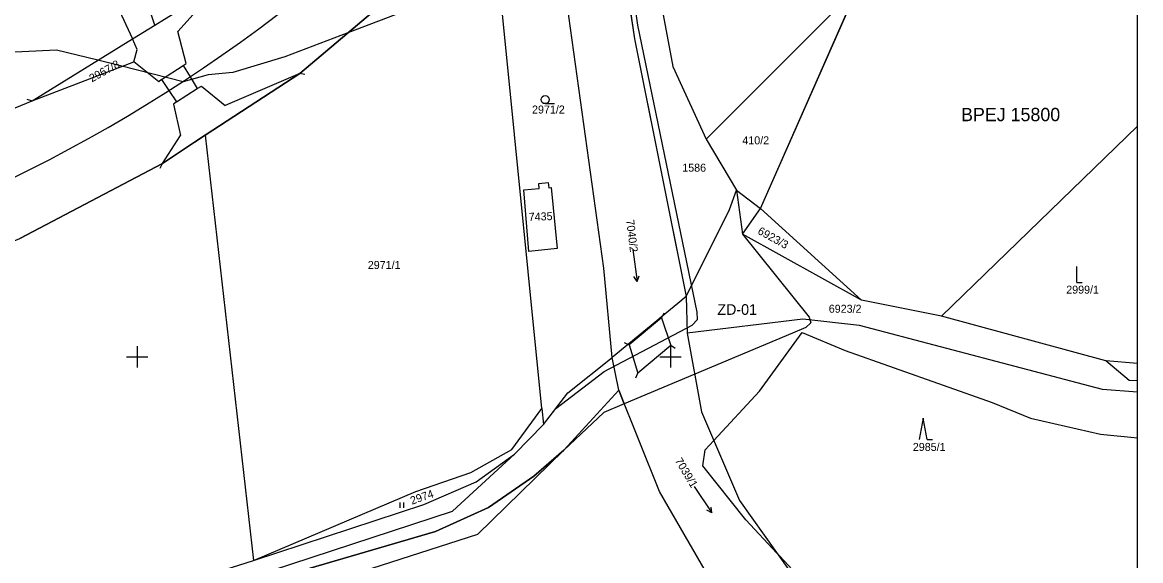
# Model space of a CAD drawing. Extents: x -800194 to -799297, y -1007177 to -1006761.
# Drawn here: x -799521.5 to -799311.8, y -1007038.2 to -1006937.3 of the extents above; entities that cross this region are included whole.
import ezdxf

# ---------------------------------------------------------------- set-up
doc = ezdxf.new("R2010")
doc.units = 0
for name, color, linetype in [('02_Osa_koleje', 7, 'Continuous'), ('BPEJ', 7, 'Continuous'), ('Dočasné zábory', 7, 'Continuous'), ('Dočasné zábory - čísla', 7, 'Continuous'), ('Legenda 1', 7, 'Continuous'), ('Pozemky SŽDC', 7, 'Continuous'), ('Ramove udaje', 7, 'Continuous'), ('Vrstva 53', 7, 'Continuous'), ('Vrstva 55', 7, 'Continuous'), ('Vrstva 56', 7, 'Continuous'), ('Vrstva 57', 7, 'Continuous'), ('Vrstva 58', 7, 'Continuous')]:
    doc.layers.add(name, color=color, linetype=linetype)

msp = doc.modelspace()

# ---------------------------------------------------------------- linework, layer by layer
at = {"layer": '02_Osa_koleje'}
msp.add_arc((-799651.02, -1006703.89), 292, 255.6249, 308.2052, dxfattribs=at)
at = {"layer": 'BPEJ'}
for points in [[(-799407.82, -1006932.95), (-799406.72, -1006940.36), (-799400.51, -1006971.29), (-799397.01, -1006988.73), (-799388.9, -1006972.36), (-799387.62, -1006968.78), (-799383.1, -1006972.22), (-799364.81, -1006930.69), (-799352.19, -1006902.04), (-799328.67, -1006848.61), (-799327.63, -1006846.25), (-799317.77, -1006827.17), (-799311.83, -1006815.65), (-799311.92, -1006815.63), (-799329.14, -1006812.3)], [(-799433.31, -1006923), (-799445.59, -1006934.44), (-799448.98, -1006934.86), (-799460.49, -1006939.26), (-799472.28, -1006943.76), (-799482.03, -1006946.72), (-799486.69, -1006947.15), (-799491.35, -1006948.42), (-799502.85, -1006945.54), (-799507.36, -1006944.41), (-799515.07, -1006942.49), (-799532.02, -1006943.33), (-799567.6, -1006955.2), (-799570.57, -1006956.47), (-799576.08, -1006956.47), (-799584.12, -1006958.16), (-799598.95, -1006964.52), (-799621.99, -1006980.43), (-799662.84, -1007008.64), (-799667.29, -1007011.71), (-799675.63, -1007017.47), (-799679.12, -1007020.67)], [(-799369.92, -1007046.57), (-799374, -1007043.32), (-799379.5, -1007037.38), (-799380.03, -1007036.82), (-799385.86, -1007030.61), (-799393.91, -1007020.44), (-799393.48, -1007017.47), (-799391.85, -1007015.71), (-799383.32, -1007006.46), (-799375.27, -1006995.44), (-799367.22, -1006998.83), (-799339.68, -1007008.58), (-799332.48, -1007011.54), (-799319.35, -1007014.51), (-799312.4, -1007015.23)]]:
    msp.add_lwpolyline(points, dxfattribs=at)
at = {"layer": 'Dočasné zábory'}
for points in [[(-799407.32, -1006903.81), (-799399.52, -1006945.6), (-799393.3, -1006959.22), (-799387.62, -1006968.78), (-799386.5, -1006977.04), (-799373.97, -1006992.55), (-799373.66, -1006993.66), (-799374.58, -1006994.49), (-799377.09, -1006995.58), (-799408.65, -1007008.83), (-799409.68, -1007006.29), (-799420, -1007017.54), (-799425.58, -1007022.42), (-799434.1, -1007028.26), (-799444.02, -1007032.78), (-799478.24, -1007042.75)], [(-799550.16, -1007064.74), (-799440.86, -1007028.93), (-799429.23, -1007018.29), (-799423.8, -1007012.71), (-799421.5, -1007009.7), (-799412.39, -1007002.78), (-799395.92, -1006994.07), (-799394.94, -1006993.03), (-799394.95, -1006991.66), (-799406.07, -1006937.82), (-799408.05, -1006924.38)]]:
    msp.add_lwpolyline(points, dxfattribs=at)
msp.add_lwpolyline([(-799605.71, -1007090.19), (-799595.06, -1007084.22), (-799551.8, -1007065.45), (-799478.24, -1007042.75), (-799444.02, -1007032.78), (-799434.1, -1007028.26), (-799425.58, -1007022.42), (-799420, -1007017.54), (-799409.68, -1007006.29), (-799408.65, -1007008.83), (-799412.5, -1007010.44), (-799420, -1007017.54), (-799436.16, -1007033.34), (-799548.49, -1007069.46), (-799592.16, -1007088.85), (-799605.02, -1007095.33)], close=True, dxfattribs=at)
at = {"layer": 'Legenda 1'}
msp.add_lwpolyline([(-800193.4, -1007176.65), (-799312.4, -1007176.65), (-799312.4, -1006766.65), (-800193.4, -1006766.65)], close=True, dxfattribs=at)
at = {"layer": 'Pozemky SŽDC'}
msp.add_lwpolyline([(-799559.64, -1006968.48), (-799519.68, -1006952.01), (-799500.87, -1006940.41), (-799496.64, -1006937.8), (-799494.85, -1006936.7), (-799484.52, -1006930.32), (-799457.99, -1006908.8), (-799435, -1006885.17), (-799430.26, -1006880.27), (-799425.53, -1006875.38), (-799422.55, -1006864.36), (-799416.75, -1006858.8), (-799395.76, -1006879.37), (-799413.75, -1006898.23), (-799418.41, -1006902.53), (-799423.07, -1006906.83), (-799433.4, -1006916.39), (-799469.5, -1006946.86), (-799487.22, -1006958.47), (-799495.25, -1006963.74), (-799521.98, -1006977.8)], dxfattribs=at)
at = {"layer": 'Ramove udaje'}
for p, q in [((-799500, -1006998), (-799500, -1007002)), ((-799400, -1006998), (-799400, -1007002)), ((-799502, -1007000), (-799500, -1007000)), ((-799500, -1007000), (-799498, -1007000)), ((-799402, -1007000), (-799400, -1007000)), ((-799400, -1007000), (-799398, -1007000))]:
    msp.add_line(p, q, dxfattribs=at)
at = {"layer": 'Vrstva 53'}
for points in [[(-799559.64, -1006968.48), (-799519.68, -1006952.01), (-799500.87, -1006940.41), (-799496.64, -1006937.8), (-799494.85, -1006936.7), (-799484.52, -1006930.32), (-799457.99, -1006908.8), (-799435, -1006885.17), (-799430.26, -1006880.27), (-799425.53, -1006875.38), (-799422.55, -1006864.36), (-799390.88, -1006834), (-799358.35, -1006806.65), (-799352.29, -1006801.56), (-799330.91, -1006783.58), (-799314.24, -1006766.65)], [(-799312.4, -1006791.98), (-799331.37, -1006811.87), (-799413.75, -1006898.23), (-799418.41, -1006902.53), (-799423.07, -1006906.83), (-799433.4, -1006916.39), (-799469.5, -1006946.86), (-799487.22, -1006958.47), (-799495.25, -1006963.74), (-799521.98, -1006977.8)]]:
    msp.add_lwpolyline(points, dxfattribs=at)
at = {"layer": 'Vrstva 55'}
for p, q in [((-799424.1, -1007009.73), (-799433.4, -1006916.39)), ((-799393.3, -1006959.22), (-799364.81, -1006930.69)), ((-799383.1, -1006972.22), (-799364.81, -1006930.69)), ((-799496.64, -1006937.8), (-799494.85, -1006936.7)), ((-799500.87, -1006940.41), (-799496.64, -1006937.8)), ((-799519.68, -1006952.01), (-799500.87, -1006940.41)), ((-799312.4, -1006956.76), (-799349.19, -1006992.39)), ((-799487.22, -1006958.47), (-799478.14, -1007038.23)), ((-799393.3, -1006959.22), (-799387.62, -1006968.78)), ((-799387.62, -1006968.78), (-799383.1, -1006972.22)), ((-799364.19, -1006989.42), (-799383.1, -1006972.22)), ((-799397.01, -1006988.73), (-799398.6, -1006990.04)), ((-799397.01, -1006988.73), (-799396.86, -1006995.59)), ((-799349.19, -1006992.39), (-799364.19, -1006989.42)), ((-799318.36, -1007000.74), (-799349.19, -1006992.39)), ((-799409.68, -1007006.29), (-799410.89, -1007000.14)), ((-799312.4, -1007001.25), (-799318.36, -1007000.74)), ((-799424.1, -1007009.73), (-799423.8, -1007012.71))]:
    msp.add_line(p, q, dxfattribs=at)
for points in [[(-799413.75, -1006898.23), (-799411.99, -1006904.75), (-799406.72, -1006940.36), (-799397.01, -1006988.73)], [(-799496.64, -1006937.8), (-799507.65, -1006904.69), (-799515.98, -1006907.74), (-799500.87, -1006940.41)], [(-799407.32, -1006903.81), (-799399.52, -1006945.6), (-799393.3, -1006959.22)], [(-799410.89, -1007000.14), (-799412.5, -1006983.38), (-799423.07, -1006906.83)], [(-799487.22, -1006958.47), (-799469.5, -1006946.86), (-799433.4, -1006916.39)], [(-799519.68, -1006952.01), (-799500.6, -1006944.68), (-799499.96, -1006942.39), (-799500.87, -1006940.41)], [(-799667.43, -1006981.06), (-799637.16, -1006982.06), (-799603.07, -1006978.39), (-799559.64, -1006968.48), (-799519.68, -1006952.01)], [(-799599.63, -1007001.65), (-799583.97, -1006998.26), (-799572.22, -1006995.8), (-799546.71, -1006987.83), (-799521.98, -1006977.8), (-799495.25, -1006963.74), (-799489.22, -1006959.79), (-799487.22, -1006958.47)], [(-799422.35, -1006968.27), (-799421.24, -1006979.68), (-799426.55, -1006980.27), (-799427.48, -1006968.72), (-799424.58, -1006968.47), (-799424.66, -1006967.5), (-799422.89, -1006967.35), (-799422.79, -1006968.31), (-799422.35, -1006968.27)], [(-799397.01, -1006988.73), (-799388.9, -1006972.36), (-799387.62, -1006968.78)], [(-799364.19, -1006989.42), (-799386.5, -1006977.04), (-799383.1, -1006972.22)], [(-799398.6, -1006990.04), (-799401.7, -1006992.59), (-799402.52, -1006993.26), (-799407.79, -1006997.59), (-799410.89, -1007000.14)], [(-799312.4, -1007006.62), (-799318.99, -1007006.15), (-799364.52, -1006994.13), (-799375.17, -1006992.97), (-799396.86, -1006995.59)], [(-799396.86, -1006995.59), (-799394.17, -1007010.32), (-799387.01, -1007026.98), (-799377.82, -1007039.94), (-799372.89, -1007045.05)], [(-799423.8, -1007012.71), (-799419.24, -1007006.74), (-799410.89, -1007000.14)], [(-799312.4, -1007004.53), (-799313.97, -1007004.43), (-799318.36, -1007000.74)], [(-799409.68, -1007006.29), (-799420, -1007017.54), (-799425.58, -1007022.42), (-799434.1, -1007028.26), (-799444.02, -1007032.78), (-799478.24, -1007042.75), (-799552.64, -1007065.71), (-799567.11, -1007070.01), (-799588.9, -1007077.33), (-799598.09, -1007080.87), (-799606.31, -1007085.7)], [(-799387.89, -1007049.68), (-799402.01, -1007025.25), (-799409.68, -1007006.29)], [(-799478.14, -1007038.23), (-799447.72, -1007025.26), (-799437.44, -1007021.73), (-799429.75, -1007017.42), (-799424.1, -1007009.73)], [(-799478.14, -1007038.23), (-799446.24, -1007027.7), (-799436.41, -1007023.44), (-799429.23, -1007018.29), (-799423.8, -1007012.71)], [(-799584.37, -1007069.36), (-799568.78, -1007065.44), (-799553.44, -1007061.89), (-799480.9, -1007039.1), (-799478.14, -1007038.23)]]:
    msp.add_lwpolyline(points, dxfattribs=at)
at = {"layer": 'Vrstva 56'}
for p, q in [((-799484.52, -1006930.32), (-799492.32, -1006939.01)), ((-799490.79, -1006945.02), (-799492.32, -1006939.01)), ((-799495.94, -1006948.45), (-799500.6, -1006944.68)), ((-799491.36, -1006945.39), (-799490.79, -1006945.02)), ((-799495.39, -1006948.04), (-799491.36, -1006945.39)), ((-799491.36, -1006945.39), (-799490.06, -1006947.5)), ((-799469.5, -1006946.86), (-799483.5, -1006952.89)), ((-799468.52, -1006947.07), (-799469.5, -1006946.86)), ((-799495.39, -1006948.04), (-799495.94, -1006948.45)), ((-799495.39, -1006948.04), (-799494.03, -1006950.08)), ((-799490.06, -1006947.5), (-799488.7, -1006949.72)), ((-799488.7, -1006949.72), (-799487.92, -1006949.28)), ((-799487.92, -1006949.28), (-799483.5, -1006952.89)), ((-799494.03, -1006950.08), (-799492.59, -1006952.23)), ((-799492.59, -1006952.23), (-799488.7, -1006949.72)), ((-799520.63, -1006951.68), (-799519.68, -1006952.01)), ((-799492.59, -1006952.23), (-799493.13, -1006952.62)), ((-799493.13, -1006952.62), (-799491.86, -1006958.5)), ((-799495.25, -1006963.74), (-799491.86, -1006958.5)), ((-799495.67, -1006964.65), (-799495.25, -1006963.74)), ((-799401.66, -1006992.7), (-799407.73, -1006997.77)), ((-799401.22, -1006991.8), (-799401.66, -1006992.7)), ((-799401.66, -1006992.7), (-799399.93, -1006997.9)), ((-799408.64, -1006997.35), (-799407.73, -1006997.77)), ((-799407.73, -1006997.77), (-799406.07, -1007003.06)), ((-799399.93, -1006997.9), (-799406.07, -1007003.06)), ((-799399.1, -1006998.46), (-799399.93, -1006997.9)), ((-799406.49, -1007003.97), (-799406.07, -1007003.06))]:
    msp.add_line(p, q, dxfattribs=at)
at = {"layer": 'Vrstva 58'}
for p, q in [((-799423.48, -1006952.54), (-799421.73, -1006952.54)), ((-799407.01, -1006979.92), (-799406.22, -1006985.87)), ((-799406.22, -1006985.87), (-799406.85, -1006984.97)), ((-799406.22, -1006985.87), (-799405.86, -1006984.83)), ((-799323.8, -1006986.09), (-799323.8, -1006983.09)), ((-799323.8, -1006986.09), (-799322.8, -1006986.09)), ((-799352.59, -1007011.5), (-799353.34, -1007015.5)), ((-799351.84, -1007015.5), (-799352.59, -1007011.5)), ((-799351.84, -1007015.5), (-799350.84, -1007015.5)), ((-799395.57, -1007024.31), (-799392.21, -1007029.28)), ((-799450.66, -1007028.34), (-799450.66, -1007027.34)), ((-799449.99, -1007028.34), (-799449.99, -1007027.34)), ((-799392.21, -1007029.28), (-799393.18, -1007028.75)), ((-799392.21, -1007029.28), (-799392.35, -1007028.19))]:
    msp.add_line(p, q, dxfattribs=at)
msp.add_circle((-799423.48, -1006951.79), 0.75, dxfattribs=at)

# ---------------------------------------------------------------- texts
at = {"layer": 'BPEJ'}
msp.add_text('BPEJ 15800', height=2.5, dxfattribs=at).set_placement((-799345.5, -1006955.83))
at = {"layer": 'Dočasné zábory - čísla'}
msp.add_text('ZD-01', height=2, rotation=0, dxfattribs=at).set_placement((-799391.19, -1006992.14))
at = {"layer": 'Vrstva 57'}
for s, rotation, p in [('2967/8', 29, (-799508.45, -1006948.57)), ('7435', 2, (-799426.53, -1006974.53)), ('7040/2', 277, (-799408.3, -1006974.37)), ('6923/3', 331, (-799383.77, -1006976.86)), ('7039/1', 301, (-799399.22, -1007019.47)), ('2974', 19, (-799448.46, -1007027.75))]:
    msp.add_text(s, height=1.5, rotation=rotation, dxfattribs=at).set_placement(p)
for s, p in [('2971/2', (-799425.94, -1006954.39)), ('410/2', (-799386.5, -1006960.17)), ('1586', (-799397.77, -1006965.3)), ('2971/1', (-799456.73, -1006983.54)), ('2999/1', (-799325.78, -1006988.17)), ('6923/2', (-799370.3, -1006991.75)), ('2985/1', (-799354.54, -1007017.66))]:
    msp.add_text(s, height=1.5, dxfattribs=at).set_placement(p)

doc.saveas('drawing.dxf')
